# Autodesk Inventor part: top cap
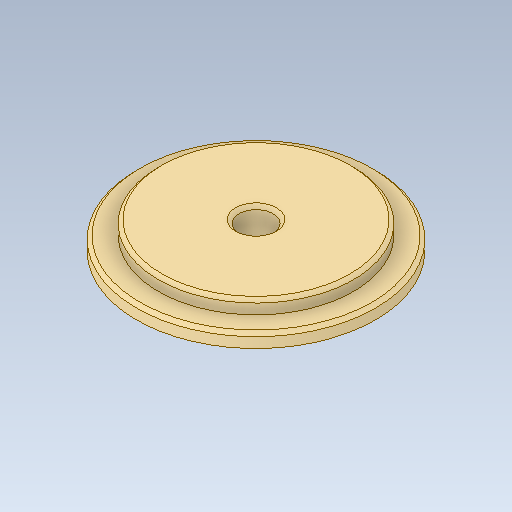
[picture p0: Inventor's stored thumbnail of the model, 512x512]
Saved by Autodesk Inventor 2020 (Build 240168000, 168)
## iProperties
Created: 2017-11
Part Number: top cap
Material: Ogólny
Document SubType Name: Modeling
Designer: Tomasz
Density: 1 g/cm^3
Appearance: Domyślna
Sending System: SolidWorks 2017
Last Author: Tomasz
Last Saved: 2017-11-19
Author: Tomasz
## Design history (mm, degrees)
feature "top cap.ipt"
node "Bryła1"
